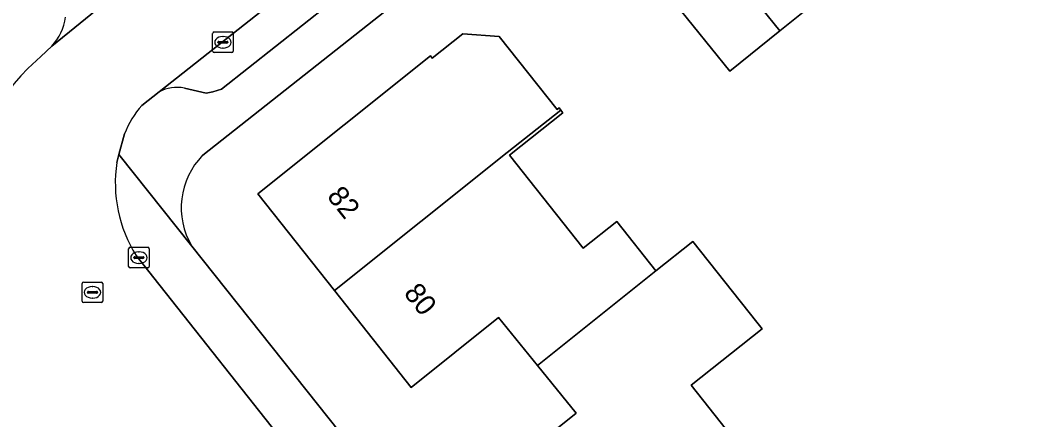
# Model space of a CAD drawing. Extents: x 157320 to 158835, y 386650 to 388491.
# Drawn here: x 157790.58 to 157840.04, y 387467.86 to 387487.24 of the extents above; entities that cross this region are included whole.
import ezdxf

# ---------------------------------------------------------------- set-up
doc = ezdxf.new("R2010")
doc.units = 0
for name, color, linetype in [('IMGEO_Erf', 7, 'Continuous'), ('IMGEO_Kolk', 7, 'Continuous'), ('IMGEO_Pand', 7, 'Continuous'), ('IMGEO_Pand_nummerreeks', 7, 'Continuous'), ('IMGEO_Parkeervlak_open', 7, 'Continuous'), ('IMGEO_Rijbaan_lokaal_open', 7, 'Continuous'), ('IMGEO_Rioolput', 7, 'Continuous'), ('IMGEO_Voetpad_open', 7, 'Continuous')]:
    doc.layers.add(name, color=color, linetype=linetype)

msp = doc.modelspace()

# ---------------------------------------------------------------- linework, layer by layer
at = {"layer": 'IMGEO_Erf'}
for points in [[(157839.124, 387512.036), (157830.533, 387505.25), (157823.234, 387499.485), (157815.987, 387493.76), (157807.747, 387487.251), (157799.439, 387480.688)], [(157813.308, 387464.739), (157817.58, 387468.17), (157815.696, 387470.49), (157813.805, 387472.819), (157809.568, 387469.423), (157805.844, 387474.121), (157802.118, 387478.821), (157810.506, 387485.511), (157810.593, 387485.401), (157812.074, 387486.578), (157813.839, 387486.46), (157816.656, 387482.913), (157816.75, 387482.988), (157816.841, 387482.873), (157816.937, 387482.753), (157814.344, 387480.692), (157817.915, 387476.183), (157819.552, 387477.48), (157821.45, 387475.083), (157823.251, 387476.51), (157826.356, 387472.591), (157826.613, 387472.266), (157823.16, 387469.531), (157825.426, 387466.67)], [(157798.908, 387476.281), (157839.999, 387424.65)]]:
    msp.add_lwpolyline(points, dxfattribs=at)
msp.add_lwpolyline([(157820.594, 387490.284), (157823.021, 387492.244), (157825.445, 387494.201), (157829.9, 387488.685), (157827.474, 387486.732), (157825.043, 387484.776)], close=True, dxfattribs=at)
msp.add_arc((157802.047, 387478.138), 3.648, 135.6499, 210.6092, dxfattribs=at)
at = {"layer": 'IMGEO_Kolk'}
for p, q in [((157799.924, 387485.748), (157799.924, 387486.6)), ((157799.999, 387486.674), (157800.851, 387486.674)), ((157800.226, 387486.217), (157800.624, 387486.217)), ((157800.412, 387486.454), (157800.437, 387486.454)), ((157800.925, 387486.6), (157800.925, 387485.748)), ((157800.183, 387486.168), (157800.183, 387486.18)), ((157800.621, 387486.131), (157800.223, 387486.131)), ((157800.435, 387485.894), (157800.41, 387485.894)), ((157800.667, 387486.18), (157800.667, 387486.168)), ((157800.851, 387485.674), (157799.999, 387485.674)), ((157795.842, 387475.295), (157795.842, 387476.147)), ((157795.917, 387476.221), (157796.769, 387476.221)), ((157796.33, 387476.001), (157796.355, 387476.001)), ((157796.843, 387476.147), (157796.843, 387475.295)), ((157796.101, 387475.715), (157796.101, 387475.727)), ((157796.539, 387475.678), (157796.141, 387475.678)), ((157796.144, 387475.764), (157796.542, 387475.764)), ((157796.353, 387475.441), (157796.328, 387475.441)), ((157796.585, 387475.727), (157796.585, 387475.715)), ((157796.769, 387475.221), (157795.917, 387475.221))]:
    msp.add_line(p, q, dxfattribs=at)
for points in [[(157799.924, 387485.748), (157799.924, 387486.6)], [(157799.999, 387486.674), (157800.851, 387486.674)], [(157800.925, 387486.6), (157800.925, 387485.748)], [(157800.851, 387485.674), (157799.999, 387485.674)], [(157795.842, 387475.295), (157795.842, 387476.147)], [(157795.917, 387476.221), (157796.769, 387476.221)], [(157796.843, 387476.147), (157796.843, 387475.295)], [(157796.769, 387475.221), (157795.917, 387475.221)]]:
    msp.add_lwpolyline(points, dxfattribs=at)
for centre, radius, start, end in [((157800.001, 387486.598), 0.0765, 91.552, 178.448), ((157800.001, 387486.598), 0.0765, 91.552, 178.448), ((157800.223, 387486.177), 0.0403, 85.8775, 175.7526), ((157800.628, 387486.179), 0.0386, 1.7309, 96.639), ((157800.849, 387486.598), 0.0765, 1.552, 88.448), ((157800.849, 387486.598), 0.0765, 1.552, 88.448), ((157800.001, 387485.75), 0.0765, 181.552, 268.448), ((157800.001, 387485.75), 0.0765, 181.552, 268.448), ((157800.22, 387486.167), 0.0366, 178.938, 274.7102), ((157800.624, 387486.174), 0.043, 264.8664, 352.4533), ((157800.849, 387485.75), 0.0765, 271.552, 358.448), ((157800.849, 387485.75), 0.0765, 271.552, 358.448), ((157795.919, 387476.145), 0.0765, 91.552, 178.448), ((157795.919, 387476.145), 0.0765, 91.552, 178.448), ((157796.767, 387476.145), 0.0765, 1.552, 88.448), ((157796.767, 387476.145), 0.0765, 1.552, 88.448), ((157796.141, 387475.724), 0.0403, 85.8775, 175.7526), ((157796.138, 387475.714), 0.0366, 178.938, 274.7102), ((157796.542, 387475.721), 0.043, 264.8664, 352.4533), ((157796.546, 387475.726), 0.0386, 1.7309, 96.639), ((157795.919, 387475.297), 0.0765, 181.552, 268.448), ((157795.919, 387475.297), 0.0765, 181.552, 268.448), ((157796.767, 387475.297), 0.0765, 271.552, 358.448), ((157796.767, 387475.297), 0.0765, 271.552, 358.448)]:
    msp.add_arc(centre, radius, start, end, dxfattribs=at)
for centre, major_axis, ratio, start_param, end_param in [((157800.411, 387486.174), (-0.387, 0.002), 0.722429, 4.712389, 7.853982), ((157800.436, 387486.174), (-0.39, 0.002), 0.717154, 1.570796, 4.712389), ((157796.329, 387475.721), (-0.387, 0.002), 0.722429, 4.712389, 7.853982), ((157796.354, 387475.721), (-0.39, 0.002), 0.717154, 1.570796, 4.712389)]:
    msp.add_ellipse(centre, major_axis=major_axis, ratio=ratio, start_param=start_param, end_param=end_param, dxfattribs=at)
at = {"layer": 'IMGEO_Pand'}
for points in [[(157827.474, 387486.732), (157829.9, 387488.685), (157825.445, 387494.201), (157823.021, 387492.244)], [(157827.474, 387486.732), (157823.021, 387492.244), (157820.594, 387490.284), (157825.043, 387484.776)], [(157805.844, 387474.121), (157814.233, 387480.819), (157816.841, 387482.873), (157816.75, 387482.988), (157816.656, 387482.913), (157813.839, 387486.46), (157812.074, 387486.578), (157810.593, 387485.401), (157810.506, 387485.511), (157802.118, 387478.821)], [(157815.696, 387470.49), (157821.45, 387475.083), (157819.552, 387477.48), (157817.915, 387476.183), (157814.344, 387480.692), (157816.937, 387482.753), (157816.841, 387482.873), (157814.233, 387480.819), (157805.844, 387474.121), (157809.568, 387469.423), (157813.805, 387472.819)], [(157815.696, 387470.49), (157817.58, 387468.17), (157813.308, 387464.739), (157817.037, 387460.026), (157825.426, 387466.67), (157823.16, 387469.531), (157826.613, 387472.266), (157826.356, 387472.591), (157823.251, 387476.51), (157821.45, 387475.083)]]:
    msp.add_lwpolyline(points, close=True, dxfattribs=at)
at = {"layer": 'IMGEO_Parkeervlak_open'}
for points in [[(157834.45, 387513.15), (157817.884, 387500), (157797.32, 387483.775)], [(157792.118, 387485.993), (157797.613, 387490.476), (157809.73, 387500), (157812.992, 387502.564), (157824.461, 387511.695)], [(157798.55, 387483.955), (157799.605, 387483.712), (157799.929, 387483.776), (157800.357, 387483.896), (157816.093, 387496.341), (157820.714, 387500), (157833.408, 387510.077)]]:
    msp.add_lwpolyline(points, dxfattribs=at)
for centre, radius, start, end in [((157790.268, 387487.721), 2.532, 316.9629, 352.4013), ((157798.21, 387481.983), 2.001, 80.2267, 116.4246)]:
    msp.add_arc(centre, radius, start, end, dxfattribs=at)
at = {"layer": 'IMGEO_Rijbaan_lokaal_open'}
for points in [[(157839.271, 387523.633), (157837.178, 387521.954), (157830.56, 387516.599), (157826.053, 387512.97), (157824.461, 387511.695), (157812.992, 387502.564), (157809.73, 387500), (157797.613, 387490.476), (157792.118, 387485.993), (157791.581, 387485.489), (157790.953, 387484.901)], [(157796.478, 387483.111), (157797.32, 387483.775), (157817.884, 387500), (157834.45, 387513.15)], [(157795.273, 387480.336), (157795.374, 387480.721), (157795.64, 387481.73)], [(157842.362, 387417.645), (157838.017, 387423.103), (157830.601, 387432.471), (157826.855, 387437.199), (157819.362, 387446.636), (157815.615, 387451.353), (157808.24, 387460.636), (157804.483, 387465.37), (157796.204, 387475.829)]]:
    msp.add_lwpolyline(points, dxfattribs=at)
for centre, radius, start, end in [((157795.793, 387479.764), 7.058, 133.2975, 196.5034), ((157800.518, 387479.715), 5.278, 139.9471, 157.5535), ((157801.765, 387479.327), 6.57, 171.1681, 212.1745)]:
    msp.add_arc(centre, radius, start, end, dxfattribs=at)
at = {"layer": 'IMGEO_Rioolput'}
for p, q in [((157793.585, 387473.61), (157793.585, 387474.462)), ((157793.66, 387474.536), (157794.512, 387474.536)), ((157794.586, 387474.462), (157794.586, 387473.61)), ((157793.844, 387474.03), (157793.844, 387474.042)), ((157794.282, 387473.993), (157793.884, 387473.993)), ((157793.887, 387474.079), (157794.285, 387474.079)), ((157794.073, 387474.316), (157794.098, 387474.316)), ((157794.328, 387474.042), (157794.328, 387474.03)), ((157794.512, 387473.536), (157793.66, 387473.536)), ((157794.096, 387473.756), (157794.071, 387473.756))]:
    msp.add_line(p, q, dxfattribs=at)
for points in [[(157793.585, 387473.61), (157793.585, 387474.462)], [(157793.66, 387474.536), (157794.512, 387474.536)], [(157794.586, 387474.462), (157794.586, 387473.61)], [(157794.512, 387473.536), (157793.66, 387473.536)]]:
    msp.add_lwpolyline(points, dxfattribs=at)
for centre, radius, start, end in [((157793.662, 387474.46), 0.0765, 91.552, 178.448), ((157793.662, 387474.46), 0.0765, 91.552, 178.448), ((157794.51, 387474.46), 0.0765, 1.552, 88.448), ((157794.51, 387474.46), 0.0765, 1.552, 88.448), ((157793.884, 387474.039), 0.0403, 85.8775, 175.7526), ((157793.881, 387474.029), 0.0366, 178.938, 274.7102), ((157794.285, 387474.036), 0.043, 264.8664, 352.4533), ((157794.289, 387474.041), 0.0386, 1.7309, 96.639), ((157793.662, 387473.612), 0.0765, 181.552, 268.448), ((157793.662, 387473.612), 0.0765, 181.552, 268.448), ((157794.51, 387473.612), 0.0765, 271.552, 358.448), ((157794.51, 387473.612), 0.0765, 271.552, 358.448)]:
    msp.add_arc(centre, radius, start, end, dxfattribs=at)
for centre, major_axis, ratio, start_param, end_param in [((157794.072, 387474.036), (-0.387, 0.002), 0.722429, 4.712389, 7.853982), ((157794.097, 387474.036), (-0.39, 0.002), 0.717154, 1.570796, 4.712389)]:
    msp.add_ellipse(centre, major_axis=major_axis, ratio=ratio, start_param=start_param, end_param=end_param, dxfattribs=at)
at = {"layer": 'IMGEO_Voetpad_open'}
for points in [[(157799.439, 387480.688), (157807.747, 387487.251), (157815.987, 387493.76), (157823.234, 387499.485), (157830.533, 387505.25), (157839.124, 387512.036)], [(157833.408, 387510.077), (157820.714, 387500), (157821.024, 387499.609), (157816.403, 387495.95), (157816.093, 387496.341), (157800.357, 387483.896), (157799.929, 387483.776), (157799.605, 387483.712), (157798.55, 387483.955)], [(157790.953, 387484.901), (157791.581, 387485.489), (157792.118, 387485.993)], [(157797.32, 387483.775), (157796.478, 387483.111)], [(157795.64, 387481.73), (157795.374, 387480.721), (157798.908, 387476.281)], [(157798.908, 387476.281), (157795.374, 387480.721), (157795.273, 387480.336)], [(157796.204, 387475.829), (157804.483, 387465.37), (157804.845, 387465.618), (157808.602, 387460.907), (157808.24, 387460.636), (157815.615, 387451.353), (157816.006, 387451.663), (157819.753, 387446.946), (157819.362, 387446.636), (157826.855, 387437.199), (157827.204, 387437.463), (157830.949, 387432.741), (157830.601, 387432.471), (157838.017, 387423.103), (157838.843, 387423.735), (157839.999, 387424.65), (157798.908, 387476.281)]]:
    msp.add_lwpolyline(points, dxfattribs=at)
for centre, radius, start, end in [((157790.268, 387487.721), 2.532, 316.9629, 352.4013), ((157795.793, 387479.764), 7.058, 133.2975, 196.5034), ((157798.21, 387481.983), 2.001, 80.2267, 116.4246), ((157800.518, 387479.715), 5.278, 139.9471, 157.5535), ((157801.765, 387479.327), 6.57, 171.1681, 212.1745), ((157802.047, 387478.138), 3.648, 135.6499, 210.6092)]:
    msp.add_arc(centre, radius, start, end, dxfattribs=at)

# ---------------------------------------------------------------- texts
at = {"layer": 'IMGEO_Pand_nummerreeks'}
for s, p in [('82', (157805.44, 387478.687)), ('80', (157809.169, 387473.983))]:
    msp.add_text(s, height=1, rotation=308.4046, dxfattribs=at).set_placement(p)

doc.saveas('drawing.dxf')
